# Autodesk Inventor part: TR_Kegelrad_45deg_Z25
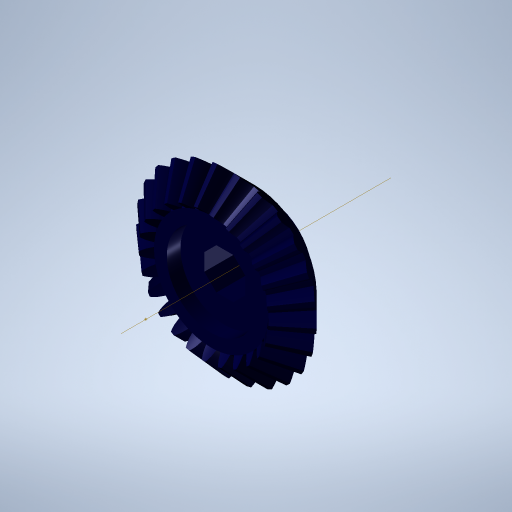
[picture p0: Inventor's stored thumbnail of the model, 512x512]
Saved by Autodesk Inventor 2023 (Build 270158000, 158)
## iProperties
CustomPartVersion: 1
Created: 2023-11
Part Number: TR_Kegelrad_45deg_Z25
Material: PBT-Kunststoff
Document SubType Name: Modeling
Designer: Admin
Categories: <?xml version="1.0" encoding="UTF-16"?> <MemberInstance><Categories><FamilyTemplate><FamilyTemplateParameter ValueType="xs:double" Id="1" ObjectReferenceKey="da
Mass: 60.9118 g
Surface Area: 34.3074 cm^2
Volume: 7.7496 cm^3
Density: 1.31 g/cm^3
Appearance: Glatt - marineblau
Author: Admin
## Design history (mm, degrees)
node "Oberster Punkt"
node "Netzebene2"
sketch "Skizze des Zahnradkörpers"
  geometry: L1 (0, 0)-(11.651, -13.349); L2 (11.651, -13.349)-(13.207, -11.793); L3 (13.207, -11.793)-(0, 0); L4 (12.5, -12.5)-(0, 0); L5 (8.356, -9.573)-(9.472, -8.457); L6 (11.651, -13.349)-(8.356, -9.573); L7 (13.207, -11.793)-(9.472, -8.457); L8 (0, -39.387)-(0, 6.564) reference; L9 (0, -12.5)-(13.207, -12.5)
  constraints: 16 end point, 4 point on line, 3 perpendicular, 2 collinear, 1 horizontal alignment, 1 vertical alignment
  dimensions: "d0" = 25 diameter of L4.start L8 (= da_de); "d1" = 23.30294 diameter of L1.end L8 (= da_dfe); "d2" = 26.41421 diameter of L2.end L8 (= da_dae); "d3" = 5 distance between parallel lines of L2 L5 (= da_b); "d4" = 11.79289 vertical distance of L2.end L1.start (= da_ve)
revolve "Zahnradkörper" sketch "Skizze des Zahnradkörpers" stored, may be unused: angle "d5" = 90 deg
node "Startpunkt"
node "Zahnebene"
sketch "Startskizze"
  geometry: L1 (0, -23.505)-(0, 10.645) reference; L2 (-0.383, -1.464)-(0.383, -1.464); A1 r 6.388 centre (-6.691, -2.474) between (-0.383, -1.464) and (-1.754, 1.58); A2 r 6.388 centre (6.691, -2.474) between (1.754, 1.58) and (0.383, -1.464); A3 r 19.338 centre (0, -17.678) between (1.754, 1.58) and (-1.754, 1.58); 1 further point
  constraints: 6 point on circle, 3 centre point, 3 symmetric about line, 2 end point, 1 coincident, 1 perpendicular, 1 other
  dimensions: "d7" = 6.38847 radius of A1 (= fd_rr); "d8" = 6.69135 horizontal distance of point (0, -17.678) A1.centre (= fd_x); "d9" = 15.20379 vertical distance of point (0, -17.678) A1.centre (= fd_y); "d57" = 19.33767 radius of A3 (= 0.5 x fd_dva + 0.3 x da_he); "d58" = 16.21367 distance from line of A3.centre L2 (= 0.5 x fd_dva - 1.12 x da_he)
node "Endpunkt"
  node "Endebene"
sketch "Endskizze"
  geometry: L1 (0, -15.354)-(0, 6.953) reference; L2 (-0.272, -1.041)-(0.272, -1.041); A1 r 4.542 centre (-4.757, -1.759) between (-0.272, -1.041) and (-1.247, 1.123); A2 r 4.542 centre (4.757, -1.759) between (1.247, 1.123) and (0.272, -1.041); A3 r 13.748 centre (0, -12.568) between (1.247, 1.123) and (-1.247, 1.123); 1 further point
  constraints: 6 point on circle, 3 centre point, 3 symmetric about line, 2 end point, 1 coincident, 1 other
  dimensions: "d12" = 4.54179 radius of A1 (computed from fd_rr, fd_ratio); "d15" = 4.75711 horizontal distance of A1.centre point (0, -12.568) (computed from fd_x, fd_ratio); "d16" = 10.8089 vertical distance of A1.centre point (0, -12.568) (computed from fd_y, fd_ratio); "d59" = 13.74782 radius of A3 (computed from d57, fd_ratio); "d60" = 11.52686 distance from line of A3.centre L2 (computed from d58, fd_ratio)
feature "Loft" sketch "Endskizze" dims "d17" = 0, "d18" = 90 deg, "d19" = 0, "d20" = 90 deg, "d89" = 0, "da_teethtype" = 0 [user parameter]
sketch "3D-Skizze rechts"
  node "Helical Curve Right" dims "d65" = 131.00537 (computed from da_dm, da_delta, da_beta), "d66" = 31.5, "d67" = 25 (= da_de), "d68" = -45 deg (= -da_delta), "d69" = 3.61332 (computed from fd_loft, da_delta)
node "Endebene rechts"
sketch "Endskizze rechts"
  geometry: L1 (0, -18.05)-(0, 9.249) reference; L2 (-0.272, -1.041)-(0.272, -1.041); A1 r 4.542 centre (-4.757, -1.759) between (-0.272, -1.041) and (-1.247, 1.123); A2 r 4.542 centre (4.757, -1.759) between (1.247, 1.123) and (0.272, -1.041); A3 r 13.748 centre (0, -12.568) between (1.247, 1.123) and (-1.247, 1.123); 1 further point
  constraints: 6 point on circle, 3 centre point, 3 symmetric about line, 2 end point, 1 coincident, 1 perpendicular, 1 other
  dimensions: "d70" = 4.75711 horizontal distance of A3.centre A1.centre (computed from fd_x, fd_ratio); "d71" = 10.8089 vertical distance of point (0, -12.568) A1.centre (computed from fd_y, fd_ratio); "d72" = 4.54179 radius of A1 (computed from fd_rr, fd_ratio); "d73" = 11.52686 distance from line of point (0, -12.568) L2 (computed from d58, fd_ratio); "d74" = 13.74782 radius of A3 (computed from d57, fd_ratio)
feature "Erhebung rechts" sketch "Endskizze rechts" dims "d75" = 0, "d77" = 0, "d79" = 0, "d80" = 90 deg, "d85" = 20, "d92" = 90 deg, "d93" = 90 deg, "da_teethtype" = 0 [user parameter]
sketch "3D-Skizze links"
  node "Helical Curve Left" dims "d26" = 131.00537 (computed from da_dm, da_delta, da_beta), "d27" = 3.61332 (computed from fd_loft, da_delta), "d28" = 25 (= da_de), "d29" = -45 deg (= -da_delta)
node "Endebene links"
sketch "Endskizze links" dims "d56" = 6.69994 (derived)
  geometry: L1 (0, -30.199)-(0, 13.176) reference; L2 (-0.272, -1.036)-(0.272, -1.036); A1 r 4.542 centre (-4.757, -1.754) between (-0.272, -1.036) and (-1.247, 1.128); A2 r 4.542 centre (4.757, -1.754) between (1.247, 1.128) and (0.272, -1.036); A3 r 13.748 centre (0, -12.563) between (1.247, 1.128) and (-1.247, 1.128); 2 further points; 1 other entity
  constraints: 6 point on circle, 3 centre point, 3 symmetric about line, 2 end point, 1 coincident, 2 other
  dimensions: "d30" = 4.54179 radius of A1 (computed from fd_rr, fd_ratio); "d31" = 4.75711 horizontal distance of point (0, -12.563) A1.centre (computed from fd_x, fd_ratio); "d32" = 10.8089 vertical distance of A1.centre point (0, -12.563) (computed from fd_y, fd_ratio); "d61" = 13.74782 radius of A3 (computed from d57, fd_ratio); "d62" = 11.52686 distance from line of point (0, -12.563) L2 (computed from d58, fd_ratio)
feature "Erhebung links" sketch "Endskizze links" dims "d35" = 0, "d37" = 0, "d39" = 0, "d40" = 90 deg, "d84" = 10, "d90" = 90 deg, "d91" = 90 deg, "da_teethtype" = 0 [user parameter]
sketch "Körperskizze"
  geometry: L1 (0, -35.038)-(0, -19.531) reference; L2 (11.651, -13.349)-(8.356, -9.573) reference; L3 (8.356, -9.573)-(0, -9.573); L4 (11.651, -13.349)-(0, -13.349)
  constraints: 4 end point, 2 perpendicular, 2 point on line
revolve "Festkörper" sketch "Körperskizze" stored, may be unused: angle "d46" = 90 deg
sketch "Sketch6"
  geometry: L1 (12.5, -12.5)-(0, 0) reference; L2 (0, -37.8)-(0, 6.3) reference
feature "Flankendurchmesser" sketch "Sketch6" dims angle "d47" = 90 deg
sketch "Skizze8"
  geometry: L1 (0, -13.349)-(11.644, -13.349); L2 (11.644, -13.349)-(9.144, -15.849); L3 (9.144, -15.849)-(6.5, -15.849); L4 (6.5, -15.849)-(6.5, -17.849); L5 (6.5, -17.849)-(0, -17.849); L6 (0, -17.849)-(0, -13.349); 2 further points
  constraints: 12 end point, 3 perpendicular, 2 coincident, 1 horizontal, 1 parallel, 1 vertical alignment
  dimensions: "d94" = 2.5 distance from line of L1 L2.end; "d95" = 2 distance of L3.end L4.end; "d96" = 6.5 distance of L4.end L5.end; "d97" = 45 deg angle of L2 L1
revolve "Umdrehung3" sketch "Skizze8" stored, may be unused: angle "d98" = 90 deg
sketch "Skizze9"
  geometry: C1 r 6.5 at (0, 0); 1 further point
  constraints: 1 centre point, 1 coincident
  dimensions: "d99" = 13 diameter of C1
extrude "Extrusion1" cut sketch "Skizze9" distance "d100" = 2; taper "d101" = 0 deg
sketch "Skizze10"
  geometry: L1 (-1.243, 3)-(1.243, 3); L2 (1.243, 3)-(3, 1.243); L3 (3, 1.243)-(3, -1.243); L4 (3, -1.243)-(1.243, -3); L5 (1.243, -3)-(-1.243, -3); L6 (-1.243, -3)-(-3, -1.243); L7 (-3, -1.243)-(-3, 1.243); L8 (-3, 1.243)-(-1.243, 3); 2 further points
  constraints: 16 end point, 1 coincident, 1 vertical, 17 other
  dimensions: "d102" = 6 distance between parallel lines of L3 L7
extrude "Extrusion2" cut sketch "Skizze10" extent not by distance; stored distance "d103" = 0; taper "d104" = 0 deg
body "Solid1"
pattern_circular "Circular Pattern" dims angle "d22" = 360 deg, "d88" = 0, "da_teethtype" = 0 [user parameter]
pattern_circular "Runde Anordnung rechts" dims angle "d82" = 360 deg, "da_teethtype" = 0 [user parameter]
pattern_circular "Runde Anordnung links" dims angle "d42" = 360 deg, "da_teethtype" = 0 [user parameter]
body "Srf1"
other parameters: "da_b" = 5 [user parameter; used in 2 equation terms], "da_de" = 25 [user parameter; used in 4 equation terms], "da_dae" = 26.41421 [user parameter; used in 2 equation terms], "da_dfe" = 23.30294 [user parameter; used in 1 equation term], "da_le" = 17.67767 [user parameter; used in 1 equation term], "da_omega" = 90 deg [user parameter; used in 1 equation term], "da_beta" = 0 [user parameter; used in 2 equation terms], "da_delta" = 45 deg [user parameter; used in 8 equation terms], "da_alpha" = 20 deg [user parameter; used in 2 equation terms], "da_he" = 2.2 [user parameter; used in 4 equation terms], "da_ve" = 11.79289 [user parameter; used in 1 equation term], "fd_dv" = 35.35534 (computed from da_de, da_delta) [user parameter; used in 1 equation term], "fd_dva" = 37.35534 (computed from da_dae, da_delta) [user parameter; used in 3 equation terms], "fd_dvb" = 33.22315 (computed from fd_dv, da_alpha) [user parameter; used in 2 equation terms], "da_zv" = 353.55339 [user parameter; used in 1 equation term], "fd_loft" = 5.11 (= da_b + 0.05 x da_he) [user parameter; used in 4 equation terms], "fd_ratio" = 7.10935 (computed from da_le, fd_loft) [user parameter; used in 15 equation terms], "fd_rr" = 6.38847 (computed from fd_dd, fd_dvb) [user parameter; used in 6 equation terms], "fd_angle" = 0.44922 (computed from da_zv) [user parameter; used in 4 equation terms], "fd_x1" = 0.79386 (computed from da_dvw, fd_angle) [user parameter; used in 1 equation term], "fd_y1" = 17.65984 (computed from da_dvw, fd_angle) [user parameter; used in 1 equation term], "fd_x2" = 5.89749 (computed from fd_rr, fd_angle2, fd_angle) [user parameter; used in 1 equation term], "fd_y2" = 2.45605 (computed from fd_rr, fd_angle2, fd_angle) [user parameter; used in 1 equation term], "fd_x" = 6.69135 (= fd_x1 + fd_x2) [user parameter; used in 4 equation terms], "fd_y" = 15.20379 (= fd_y1 - fd_y2) [user parameter; used in 4 equation terms], "fd_angle2" = 3.49689 (computed from fd_dvb, fd_dd, da_alpha) [user parameter; used in 2 equation terms], "fd_dd" = 35.59534 (= fd_dva - 0.8 x da_he) [user parameter; used in 2 equation terms], "da_dvw" = 35.35534 [user parameter; used in 2 equation terms], "d11" = 5.11 (= fd_loft), "da_dm" = 21.46447 [user parameter; used in 2 equation terms], "da_x" = 0 [user parameter], "da_m" = 1 [user parameter], "d48" = 0, "d49" = 0, "d50" = 90 deg (= da_omega), "d51" = 1.25664 (computed from da_z), "d52" = 0, "d53" = 0, "d54" = 0
